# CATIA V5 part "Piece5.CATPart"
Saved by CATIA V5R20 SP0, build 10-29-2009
Part number: Piece5
Bounding box of the stored display mesh (mm): x 0 to 20, y 0 to 52.685, z -81.982 to -63
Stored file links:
  C:\Users\ASUS\Desktop\Think Motion IAO\Piece5.CATPart
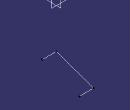
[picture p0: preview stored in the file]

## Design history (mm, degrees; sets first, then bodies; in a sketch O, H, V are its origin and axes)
Body1 (main body)
  Point1 "Point.E": stored without definition
  Line1: type PtDir, RefPoint Point1, Direction yz-plane, Start 0, End 20
  Point2 "Point.G": stored without definition
  Line2: type PtDir, RefPoint Point2, Direction yz-plane, Start 0, End 20
  Point3 "Point.G": stored without definition
  Point4 "Point.E": stored without definition
  Line3: type PtPt, FirstPoint Point3, SecondPoint Point4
